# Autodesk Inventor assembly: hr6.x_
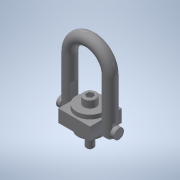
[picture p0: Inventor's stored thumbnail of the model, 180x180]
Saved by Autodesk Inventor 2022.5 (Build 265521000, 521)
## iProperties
Part Number: hr6.x_
Material: 一般
Document SubType Name: Assembly
Designer: ImaoCorp
Sending System: SOLIDWORKS 2017-2017317
MC: AMD64
MC_MODEL: Intel64 Family 6 Model 60 Stepping 3, GenuineIntel
OS: Windows_NT
FRU: Parasolid Version 29.0, build 201,  4-17-2017
FORMAT: text
GUISE: transmit
KEY: hr6
FILE: hr6.x_t
DATE: Mon Jul 01 17:38:38 2019
Author: ImaoCorp
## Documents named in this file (3)
- X:\14_SW2022-Inv2022\00_全2023-1023新製品(TCC)まで\h\hr6\HR6.iam
- X:\14_SW2022-Inv2022\00_全2023-1023新製品(TCC)まで\h\hr6\hr6_01.ipt
- X:\14_SW2022-Inv2022\00_全2023-1023新製品(TCC)まで\h\hr6\hr6_02.ipt
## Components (2 placed, 2 different names)
1. hr6_01
2. hr6_02
